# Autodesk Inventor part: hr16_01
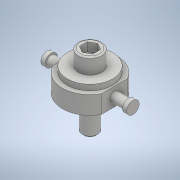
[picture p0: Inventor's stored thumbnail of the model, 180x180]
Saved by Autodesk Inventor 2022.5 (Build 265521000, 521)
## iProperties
Part Number: hr16_01
Material: 一般
Document SubType Name: Modeling
Designer: ImaoCorp
Density: 1 g/cm^3
Appearance: 既定
Author: ImaoCorp
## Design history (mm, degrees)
feature "hr16_01"
node "ソリッド1"
